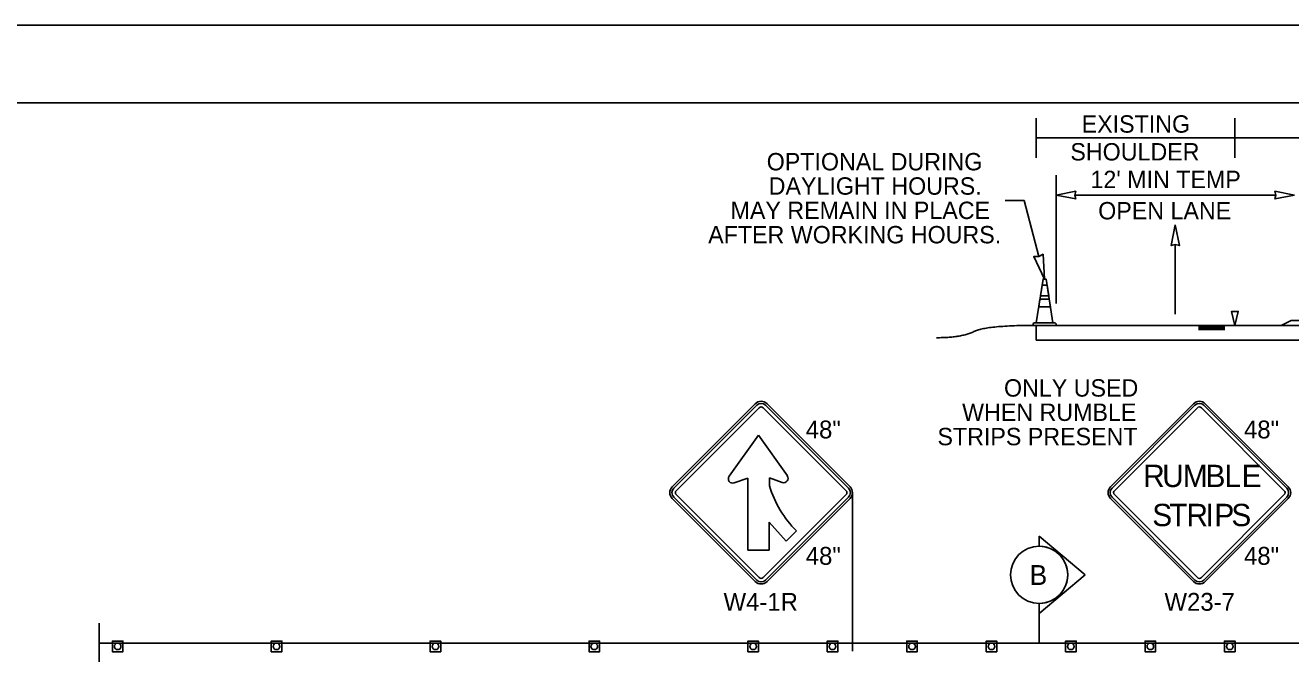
# Model space of a CAD drawing. Extents: x 99999 to 100116, y 99995 to 100013.
# Drawn here: x 100067.9 to 100072.99, y 100008.16 to 100010.69 of the extents above; entities that cross this region are included whole.
import ezdxf

# ---------------------------------------------------------------- set-up
doc = ezdxf.new("R2010")
doc.units = 0
for name, color, linetype in [('SH_GI_PlotLimits', 7, 'Continuous'), ('SH_GI_SectionCut', 7, 'Continuous'), ('SH_GI_SheetBorder', 7, 'Continuous'), ('SH_TI_WZSectionCut', 7, 'Continuous'), ('TR_SN_ConstructionSigns', 7, 'Continuous'), ('TR_WZ_ArrowLeftStrRightTurn', 7, 'Continuous'), ('TR_WZ_TrafficCone', 7, 'Continuous'), ('TR_WZ_TrafficConeElev', 7, 'Continuous'), ('TR_WZ_TrafficSafetyDrumElev', 7, 'Continuous'), ('TR_WZ_WorkZoneDetails', 7, 'Continuous'), ('TR_WZ_WorkZoneTextCurrent', 7, 'Continuous')]:
    doc.layers.add(name, color=color, linetype=linetype)

msp = doc.modelspace()

# ---------------------------------------------------------------- linework, layer by layer
at = {"layer": 'SH_GI_PlotLimits'}
msp.add_lwpolyline([(100059.0625, 99999.6875), (100076.0625, 99999.6875), (100076.0625, 100010.6875), (100059.0625, 100010.6875)], close=True, dxfattribs=at)
at = {"layer": 'SH_GI_SectionCut'}
for p, q in [((100071.9814, 100008.589), (100071.9814, 100008.6297)), ((100071.9814, 100008.6297), (100072.1675, 100008.4738)), ((100072.1675, 100008.4738), (100071.9814, 100008.3179)), ((100071.9814, 100008.3179), (100071.9814, 100008.3586)), ((100071.9814, 100008.3179), (100071.9814, 100008.1989))]:
    msp.add_line(p, q, dxfattribs=at)
msp.add_circle((100071.9814, 100008.4738), 0.1152, dxfattribs=at)
msp.add_circle((100071.9814, 100008.4738), 0.1152, dxfattribs=at)
for start, end in [(90.0016, 269.9972), (269.9972, 90.0016), (269.9972, 90.0016)]:
    msp.add_arc((100071.9814, 100008.4738), 0.1152, start, end, dxfattribs=at)
at = {"layer": 'SH_GI_SheetBorder'}
msp.add_line((100060, 100010.375), (100075.75, 100010.375), dxfattribs=at)
at = {"layer": 'SH_TI_WZSectionCut'}
for p, q in [((100072.05, 100009.5666), (100072.05, 100010.0836)), ((100072.125, 100010.0036), (100072.935, 100010.0036))]:
    msp.add_line(p, q, dxfattribs=at)
for points in [[(100072.05, 100010.0036), (100072.1286, 100009.9882), (100072.125, 100010.0036), (100072.1286, 100010.019)], [(100073.01, 100010.0036), (100072.9314, 100009.9882), (100072.935, 100010.0036), (100072.9314, 100010.019)]]:
    msp.add_lwpolyline(points, close=True, dxfattribs=at)
at = {"layer": 'TR_SN_ConstructionSigns'}
for p, q in [((100070.8376, 100009.1627), (100070.5035, 100008.8286)), ((100070.8436, 100009.1568), (100070.5095, 100008.8227)), ((100070.5194, 100008.8127), (100070.8536, 100009.1468)), ((100070.8695, 100009.1468), (100071.2036, 100008.8127)), ((100071.2135, 100008.8227), (100070.8794, 100009.1568)), ((100071.2195, 100008.8286), (100070.8854, 100009.1627)), ((100072.6031, 100009.1627), (100072.269, 100008.8286)), ((100072.6091, 100009.1568), (100072.275, 100008.8227)), ((100072.2849, 100008.8127), (100072.619, 100009.1468)), ((100072.6349, 100009.1468), (100072.969, 100008.8127)), ((100072.979, 100008.8227), (100072.6449, 100009.1568)), ((100072.9849, 100008.8286), (100072.6508, 100009.1627)), ((100070.7327, 100008.871), (100070.8506, 100009.0367)), ((100070.8506, 100009.0367), (100070.9671, 100008.8728)), ((100070.8079, 100008.8629), (100070.753, 100008.8439)), ((100070.8079, 100008.5728), (100070.8079, 100008.8629)), ((100070.9466, 100008.8458), (100070.8947, 100008.8644)), ((100070.8947, 100008.8644), (100070.8947, 100008.832)), ((100070.5095, 100008.7869), (100070.8436, 100008.4528)), ((100070.8536, 100008.4627), (100070.5194, 100008.7968)), ((100071.2036, 100008.7968), (100070.8695, 100008.4627)), ((100070.8794, 100008.4528), (100071.2135, 100008.7869)), ((100072.275, 100008.7869), (100072.6091, 100008.4528)), ((100072.619, 100008.4627), (100072.2849, 100008.7968)), ((100072.969, 100008.7968), (100072.6349, 100008.4627)), ((100072.6449, 100008.4528), (100072.979, 100008.7869)), ((100070.5035, 100008.7809), (100070.8376, 100008.4468)), ((100070.8854, 100008.4468), (100071.2195, 100008.7809)), ((100072.269, 100008.7809), (100072.6031, 100008.4468)), ((100072.6508, 100008.4468), (100072.9849, 100008.7809)), ((100070.9624, 100008.6097), (100070.8932, 100008.6862)), ((100070.8932, 100008.6862), (100070.8932, 100008.5728)), ((100071.0036, 100008.6509), (100070.9624, 100008.6097)), ((100070.8932, 100008.5728), (100070.8079, 100008.5728))]:
    msp.add_line(p, q, dxfattribs=at)
for centre, radius, start, end in [((100070.8615, 100009.1389), 0.0338, 45, 135), ((100070.8615, 100009.1389), 0.0253, 45, 135), ((100070.8615, 100009.1389), 0.0113, 45, 135), ((100072.627, 100009.1389), 0.0338, 45, 135), ((100072.627, 100009.1389), 0.0253, 45, 135), ((100072.627, 100009.1389), 0.0113, 45, 135), ((100070.7472, 100008.8607), 0.0177, 144.5862, 289.1062), ((100070.9526, 100008.8626), 0.0177, 250.3331, 35.4138), ((100070.5274, 100008.8048), 0.0338, 135, 225), ((100070.5274, 100008.8048), 0.0253, 135, 225), ((100070.5274, 100008.8048), 0.0113, 135, 225), ((100071.3078, 100008.9571), 0.4316, 196.843, 225.185), ((100071.1956, 100008.8048), 0.0113, 315, 45), ((100071.1956, 100008.8048), 0.0253, 315, 45), ((100071.1956, 100008.8048), 0.0338, 315, 45), ((100072.2929, 100008.8048), 0.0338, 135, 225), ((100072.2929, 100008.8048), 0.0253, 135, 225), ((100072.2929, 100008.8048), 0.0113, 135, 225), ((100072.9611, 100008.8048), 0.0113, 315, 45), ((100072.9611, 100008.8048), 0.0253, 315, 45), ((100072.9611, 100008.8048), 0.0338, 315, 45), ((100070.8615, 100008.4707), 0.0338, 225, 315), ((100070.8615, 100008.4707), 0.0253, 225, 315), ((100070.8615, 100008.4707), 0.0113, 225, 315), ((100072.627, 100008.4707), 0.0338, 225, 315), ((100072.627, 100008.4707), 0.0253, 225, 315), ((100072.627, 100008.4707), 0.0113, 225, 315)]:
    msp.add_arc(centre, radius, start, end, dxfattribs=at)
at = {"layer": 'TR_WZ_ArrowLeftStrRightTurn'}
msp.add_line((100072.53, 100009.8039), (100072.53, 100009.524), dxfattribs=at)
msp.add_lwpolyline([(100072.53, 100009.884), (100072.5135, 100009.8), (100072.53, 100009.8039), (100072.5465, 100009.8)], close=True, dxfattribs=at)
at = {"layer": 'TR_WZ_TrafficCone'}
for points in [[(100068.2481, 100008.2069), (100068.2907, 100008.2069), (100068.2907, 100008.1642), (100068.2481, 100008.1642), (100068.2481, 100008.2069)], [(100068.2481, 100008.1642), (100068.2907, 100008.1642), (100068.2907, 100008.2069), (100068.2481, 100008.2069), (100068.2481, 100008.1642)], [(100068.8881, 100008.2069), (100068.9307, 100008.2069), (100068.9307, 100008.1642), (100068.8881, 100008.1642), (100068.8881, 100008.2069)], [(100068.8881, 100008.1642), (100068.9307, 100008.1642), (100068.9307, 100008.2069), (100068.8881, 100008.2069), (100068.8881, 100008.1642)], [(100069.5281, 100008.2069), (100069.5707, 100008.2069), (100069.5707, 100008.1642), (100069.5281, 100008.1642), (100069.5281, 100008.2069)], [(100069.5281, 100008.1642), (100069.5707, 100008.1642), (100069.5707, 100008.2069), (100069.5281, 100008.2069), (100069.5281, 100008.1642)], [(100070.1681, 100008.2069), (100070.2107, 100008.2069), (100070.2107, 100008.1642), (100070.1681, 100008.1642), (100070.1681, 100008.2069)], [(100070.1681, 100008.1642), (100070.2107, 100008.1642), (100070.2107, 100008.2069), (100070.1681, 100008.2069), (100070.1681, 100008.1642)], [(100070.8081, 100008.2069), (100070.8507, 100008.2069), (100070.8507, 100008.1642), (100070.8081, 100008.1642), (100070.8081, 100008.2069)], [(100070.8081, 100008.1642), (100070.8507, 100008.1642), (100070.8507, 100008.2069), (100070.8081, 100008.2069), (100070.8081, 100008.1642)], [(100071.1281, 100008.2069), (100071.1707, 100008.2069), (100071.1707, 100008.1642), (100071.1281, 100008.1642), (100071.1281, 100008.2069)], [(100071.1281, 100008.1642), (100071.1707, 100008.1642), (100071.1707, 100008.2069), (100071.1281, 100008.2069), (100071.1281, 100008.1642)], [(100071.4481, 100008.2069), (100071.4907, 100008.2069), (100071.4907, 100008.1642), (100071.4481, 100008.1642), (100071.4481, 100008.2069)], [(100071.4481, 100008.1642), (100071.4907, 100008.1642), (100071.4907, 100008.2069), (100071.4481, 100008.2069), (100071.4481, 100008.1642)], [(100071.7681, 100008.2069), (100071.8107, 100008.2069), (100071.8107, 100008.1642), (100071.7681, 100008.1642), (100071.7681, 100008.2069)], [(100071.7681, 100008.1642), (100071.8107, 100008.1642), (100071.8107, 100008.2069), (100071.7681, 100008.2069), (100071.7681, 100008.1642)], [(100072.0881, 100008.2069), (100072.1307, 100008.2069), (100072.1307, 100008.1642), (100072.0881, 100008.1642), (100072.0881, 100008.2069)], [(100072.0881, 100008.1642), (100072.1307, 100008.1642), (100072.1307, 100008.2069), (100072.0881, 100008.2069), (100072.0881, 100008.1642)], [(100072.4081, 100008.2069), (100072.4507, 100008.2069), (100072.4507, 100008.1642), (100072.4081, 100008.1642), (100072.4081, 100008.2069)], [(100072.4081, 100008.1642), (100072.4507, 100008.1642), (100072.4507, 100008.2069), (100072.4081, 100008.2069), (100072.4081, 100008.1642)], [(100072.7281, 100008.2069), (100072.7707, 100008.2069), (100072.7707, 100008.1642), (100072.7281, 100008.1642), (100072.7281, 100008.2069)], [(100072.7281, 100008.1642), (100072.7707, 100008.1642), (100072.7707, 100008.2069), (100072.7281, 100008.2069), (100072.7281, 100008.1642)]]:
    msp.add_lwpolyline(points, dxfattribs=at)
for centre in [(100068.2694, 100008.1856), (100068.9094, 100008.1856), (100069.5494, 100008.1856), (100070.1894, 100008.1856), (100070.8294, 100008.1856), (100071.1494, 100008.1856), (100071.4694, 100008.1856), (100071.7894, 100008.1856), (100072.1094, 100008.1856), (100072.4294, 100008.1856), (100072.7494, 100008.1856)]:
    msp.add_circle(centre, 0.0133, dxfattribs=at)
at = {"layer": 'TR_WZ_TrafficConeElev'}
for p, q in [((100071.9866, 100009.5971), (100071.9933, 100009.6404)), ((100071.9933, 100009.6404), (100072.0134, 100009.6404)), ((100072.0134, 100009.6404), (100072.0201, 100009.5971)), ((100071.98, 100009.5537), (100071.9846, 100009.5837)), ((100072.0267, 100009.5537), (100071.98, 100009.5537)), ((100071.9846, 100009.5837), (100072.0221, 100009.5837)), ((100072.0201, 100009.5971), (100071.9866, 100009.5971)), ((100072.0221, 100009.5837), (100072.0267, 100009.5537)), ((100071.9571, 100009.4854), (100071.9604, 100009.4887)), ((100071.9571, 100009.4787), (100071.9571, 100009.4854)), ((100072.0496, 100009.4787), (100071.9571, 100009.4787)), ((100072.0367, 100009.4887), (100072.0462, 100009.4887)), ((100072.0462, 100009.4887), (100072.0496, 100009.4854)), ((100072.0496, 100009.4854), (100072.0496, 100009.4787))]:
    msp.add_line(p, q, dxfattribs=at)
msp.add_lwpolyline([(100072.0367, 100009.4887), (100071.97, 100009.4887), (100071.9971, 100009.6654), (100072.0096, 100009.6654)], close=True, dxfattribs=at)
msp.add_lwpolyline([(100072.0367, 100009.4887), (100071.97, 100009.4887), (100071.9971, 100009.6654), (100072.0096, 100009.6654)], close=True, dxfattribs=at)
msp.add_lwpolyline([(100071.9604, 100009.4887), (100071.97, 100009.4887), (100072.0367, 100009.4887)], dxfattribs=at)
at = {"layer": 'TR_WZ_TrafficSafetyDrumElev'}
msp.add_lwpolyline([(100072.9559, 100009.4788), (100072.9961, 100009.4988), (100073.1557, 100009.4988), (100073.1959, 100009.4788)], close=True, dxfattribs=at)
at = {"layer": 'TR_WZ_WorkZoneDetails'}
for p, q in [((100071.97, 100010.154), (100071.97, 100010.314)), ((100072.77, 100010.154), (100072.77, 100010.314)), ((100071.97, 100010.234), (100072.77, 100010.234)), ((100072.77, 100010.234), (100073.73, 100010.234)), ((100071.8452, 100009.9811), (100071.9214, 100009.9811)), ((100071.9798, 100009.7561), (100071.9214, 100009.9811)), ((100075.65, 100009.4787), (100071.97, 100009.4787)), ((100071.97, 100009.4787), (100071.97, 100009.4187)), ((100072.6236, 100009.4746), (100072.73, 100009.4746)), ((100072.6236, 100009.4701), (100072.73, 100009.4701)), ((100072.6236, 100009.4655), (100072.73, 100009.4655)), ((100072.6236, 100009.4614), (100072.73, 100009.4614)), ((100075.65, 100009.4187), (100071.97, 100009.4187)), ((100071.2294, 100008.1669), (100071.2294, 100008.8048)), ((100068.195, 100008.1989), (100075.43, 100008.1989))]:
    msp.add_line(p, q, dxfattribs=at)
for points in [[(100072.0033, 100009.6654), (100071.96, 100009.7557), (100071.9798, 100009.7561), (100071.9974, 100009.7654)], [(100072.77, 100009.4787), (100072.7566, 100009.5346), (100072.7833, 100009.5346)]]:
    msp.add_lwpolyline(points, close=True, dxfattribs=at)
for points in [[(100072.7833, 100009.5346), (100072.7566, 100009.5346), (100072.77, 100009.4787), (100072.7833, 100009.5346)], [(100068.195, 100006.7109), (100068.195, 100007.433), (100068.131, 100007.433), (100068.259, 100007.5569), (100068.195, 100007.5569), (100068.195, 100008.2789)]]:
    msp.add_lwpolyline(points, dxfattribs=at)
msp.add_open_spline([(100071.97, 100009.4787), (100071.7691, 100009.4787), (100071.6687, 100009.429), (100071.5683, 100009.429)], degree=2, dxfattribs=at)

# ---------------------------------------------------------------- texts
at = {"layer": 'SH_GI_SectionCut'}
msp.add_text('B', height=0.08, rotation=0.0094, dxfattribs=at).set_placement((100071.9427, 100008.4331))
at = {"layer": 'TR_SN_ConstructionSigns'}
for s, height, p in [('48"', 0.072, (100071.0413, 100009.0233)), ('48"', 0.072, (100072.8068, 100009.0233)), ('R', 0.09, (100072.4006, 100008.8273)), ('U', 0.09, (100072.4771, 100008.8273)), ('M', 0.09, (100072.5599, 100008.8273)), ('B', 0.09, (100072.6517, 100008.8273)), ('L', 0.09, (100072.7282, 100008.8273)), ('E', 0.09, (100072.7975, 100008.8273)), ('S', 0.09, (100072.4371, 100008.6698)), ('T', 0.09, (100072.5055, 100008.6698)), ('R', 0.09, (100072.5748, 100008.6698)), ('I', 0.09, (100072.6513, 100008.6698)), ('P', 0.09, (100072.6873, 100008.6698)), ('S', 0.09, (100072.7557, 100008.6698)), ('48"', 0.072, (100071.0413, 100008.5142)), ('48"', 0.072, (100072.8068, 100008.5142)), ('W4-1R', 0.072, (100070.7101, 100008.3289)), ('W23-7', 0.072, (100072.4864, 100008.3289))]:
    msp.add_text(s, height=height, rotation=360, dxfattribs=at).set_placement(p)
at = {"layer": 'TR_WZ_WorkZoneDetails'}
for s, p in [('EXISTING', (100072.1527, 100010.255)), ('SHOULDER', (100072.1073, 100010.143)), ("12' MIN TEMP", (100072.1882, 100010.0316)), ('OPEN LANE', (100072.2194, 100009.9056)), ('ONLY USED', (100071.8399, 100009.1917)), ('WHEN RUMBLE', (100071.6711, 100009.0937)), ('STRIPS PRESENT', (100071.5718, 100008.9957))]:
    msp.add_text(s, height=0.07, dxfattribs=at).set_placement(p)
at = {"layer": 'TR_WZ_WorkZoneTextCurrent'}
for s, p in [('OPTIONAL DURING', (100070.884, 100010.1031)), ('DAYLIGHT HOURS.', (100070.8919, 100010.0051)), ('MAY REMAIN IN PLACE', (100070.7383, 100009.9071)), ('AFTER WORKING HOURS.', (100070.6481, 100009.8091))]:
    msp.add_text(s, height=0.07, dxfattribs=at).set_placement(p)

doc.saveas('drawing.dxf')
